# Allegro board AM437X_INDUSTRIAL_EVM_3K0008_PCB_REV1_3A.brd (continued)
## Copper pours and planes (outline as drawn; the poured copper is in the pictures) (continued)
(no net) on BOTTOM: 123.7,66.8 123.7,66.17 121.41,63.88 118.75,63.88 118.49,64.14 118.49,65.15 118.75,65.41 120.02,65.41 120.33,65.72 120.33,67.24 120.91,67.82 122.68,67.82
(no net) on BOTTOM: 120.4,79.63 114.43,79.63 113.66,78.87 112.27,78.87 112.01,79.12 112.01,79.5 114.68,82.17 115.19,82.17 116.33,83.31 116.33,84.45 118.24,86.36 118.24,86.74 118.62,87.12 120.14,87.12 120.65,86.61 120.65,79.88
(no net) on BOTTOM: 52.2,54.61 51.56,53.98 49.66,53.98 49.15,54.48 49.15,56.77 50.93,58.55 51.94,58.55 52.2,58.29
(no net) on BOTTOM: 52.32,76.83 51.43,75.95 49.78,75.95 49.28,76.45 49.28,78.99 51.05,80.77 52.07,80.77 52.32,80.52
(no net) on BOTTOM: 116.08,61.78 116.08,57.91 117.23,56.77 117.23,55.63 117.1,55.5 113.29,55.5 113.16,55.63 113.16,58.17 112.15,59.18 111.51,59.18 110.88,59.81 110.88,66.68 112.78,68.58 114.81,68.58 115.19,68.2 117.23,68.2 117.61,68.58 119.64,68.58 119.89,68.33 119.89,65.86 119.7,65.66 115.63,65.66 115.25,65.28 115.25,62.61
(no net) on BOTTOM: 120.52,77.85 114.3,77.85 113.79,77.34 113.79,72.64 114.17,72.26 118.62,72.26 121.03,74.68 121.03,77.34
(no net) on BOTTOM: 113.16,85.34 115.44,85.34 115.7,85.6 115.7,89.28 115.44,89.53 113.28,89.53 112.9,89.15 112.9,85.6
(no net) on BOTTOM: 54.99,72.52 54.99,69.98 54.36,69.34 52.96,69.34 52.45,69.85 52.45,73.91 52.7,74.17 53.34,74.17
(no net) on BOTTOM: 43.05,47.75 44.58,47.75 44.83,47.5 44.83,46.48 44.58,46.23 43.56,46.23 42.8,46.99 42.8,47.5
(no net) on BOTTOM: 113.28,83.44 113.03,83.69 113.03,84.71 113.28,84.96 114.43,84.96 115.06,84.33 115.06,83.69 114.81,83.44
(no net) on BOTTOM: 129.85,66.64 129.85,67.82 130.11,68.07 133.03,68.07 133.28,67.82 133.28,66.55 133.03,66.29 130.2,66.29
(no net) on BOTTOM: 121.41,82.55 124.08,82.55 124.46,82.93 124.46,86.11 124.08,86.49 121.41,86.49 121.03,86.11 121.03,82.93
(no net) on BOTTOM: 37.34,53.34 43.56,53.34 44.07,53.85 44.07,58.55 43.56,59.05 39.37,59.05 36.83,56.52 36.83,53.85
(no net) on BOTTOM: 44.7,45.85 42.42,45.85 42.16,45.59 42.16,41.91 42.42,41.66 44.58,41.66 44.96,42.04 44.96,45.59
(no net) on BOTTOM: 118.24,40.51 112.01,40.51 111.51,40 111.51,35.31 111.76,35.05 116.46,35.05 118.75,37.34 118.75,40
(no net) on BOTTOM: 109.6,51.18 98.68,51.18 97.92,50.42 97.92,48.64 98.42,48.13 103.12,48.13 103.63,47.62 103.63,45.47 104.52,44.58 109.6,44.58 110.24,45.21 110.24,50.55
(no net) on BOTTOM: 59.31,109.98 60.58,111.25 63.25,111.25 63.5,111.51 66.8,111.51 67.06,111.25 67.06,110.24 66.8,109.98 64.64,109.98 61.85,107.19 61.85,105.79 62.1,105.54 62.74,105.54 62.99,105.28 62.99,104.77 60.96,102.74 54.86,102.74 53.34,104.27 53.26,104.27 53.26,106.55 56.69,109.98
(no net) on BOTTOM: 116.59,61.85 119.13,61.85 119.64,61.34 121.66,61.34 121.92,61.09 121.92,60.71 121.67,60.45 116.84,60.45 116.59,60.71
(no net) on BOTTOM: 124.33,59.94 130.82,59.94 131.57,59.19 131.57,54.1 129.8,52.32 124.59,52.32 123.57,53.34 123.57,59.18
(no net) on BOTTOM: 110.87,48.01 113.16,48.01 113.41,48.26 113.41,51.94 113.16,52.2 111,52.2 110.62,51.82 110.62,48.26
(no net) on BOTTOM: 36.7,48.39 33.66,48.39 33.4,48.13 33.4,45.09 33.78,44.7 36.45,44.7 36.83,45.09 36.83,48.26
(no net) on BOTTOM: 22.48,67.06 26.03,67.06 26.29,66.8 26.29,65.79 26.03,65.53 25.15,65.53 23.62,64.01 22.48,64.01 22.1,64.39 22.1,66.67
(no net) on BOTTOM: 119.13,45.21 121.79,45.21 122.17,45.59 122.17,48.77 121.79,49.15 119.13,49.15 118.75,48.77 118.75,45.59
(no net) on BOTTOM: 52.2,64.14 51.31,63.25 49.66,63.25 49.15,63.75 49.15,66.29 50.8,67.95 51.94,67.95 52.2,67.69
(no net) on BOTTOM: 138.66,66.04 138.66,70.1 138.27,70.48 135.06,70.48 134.81,70.23 134.81,65.41 135.19,65.02 136.84,65.02 136.97,65.15 136.97,66.04
(no net) on BOTTOM: 114.17,104.01 110.62,104.01 110.49,103.89 110.49,102.49 110.74,102.23 117.35,102.23 117.6,102.49 117.6,104.27 117.47,104.39 114.55,104.39
(no net) on BOTTOM: 22.48,92.33 25.91,92.33 26.03,92.2 26.03,91.06 25.78,90.8 25.15,90.8 23.62,89.28 22.48,89.28 22.1,89.66 22.1,91.95
(no net) on BOTTOM: 20.57,56.64 20.57,52.83 19.94,52.2 9.4,52.2 8.89,52.7 8.89,55.24 9.4,55.75 13.46,55.75 14.99,57.28 19.94,57.28
AM437X_VDDS on L4_SIG2: 75.56,72.77 76.33,72.01 86.36,72.01 87.25,71.12 87.25,66.22 73.91,66.22 73.28,65.59 73.28,64.77 74.3,63.75 76.71,63.75 77.85,62.61 77.85,61.34 76.38,59.87 69.55,59.87 67.69,61.72 67.69,69.09 70.48,71.88 74.17,71.88 75.06,72.77
FTDI_VPHY on BOTTOM (solid shape): 121.8,59.18 121.8,58.42 121.67,58.3 120.78,58.3 120.65,58.42 120.27,58.42 119.77,58.42 119.51,58.42 119.26,58.17 116.72,58.17 116.72,59.57 116.84,59.69 121.29,59.69
FTDI_VPLL on BOTTOM (solid shape): 119.64,61.34 120.27,61.34 121.66,61.34 121.92,61.09 121.92,60.86 121.52,60.45 116.84,60.45 116.59,60.71 116.59,61.85 119.13,61.85
MOT_OUT1 on TOP (solid shape): 40.89,28.07 40.91,28.05 40.91,27.25 41.07,27.08 41.07,26.89 41.08,26.82 41.1,26.76 41.12,26.7 41.15,26.64 41.19,26.59 41.24,26.54 41.29,26.49 41.32,26.48 41.32,25.82 36.45,20.95 36.45,19.05 34.16,16.76 30.48,16.76 29.84,17.4 29.84,19.56 34.92,24.64 36.45,24.64 36.45,24.58 36.46,24.53 36.48,24.48 36.51,24.43 36.55,24.38 36.59,24.34 36.63,24.31 36.68,24.29 36.73,24.27 36.79,24.26 36.84,24.26 36.9,24.26 36.95,24.28 37,24.3 37.05,24.33 37.1,24.36 37.13,24.4 37.16,24.45 37.19,24.5 37.2,24.55 37.21,24.61 37.21,24.67 37.2,24.72 37.19,24.77 37.16,24.82 37.13,24.87 37.1,24.91 37.05,24.95 37,24.98 36.95,25 36.9,25.01 36.84,25.02 36.79,25.02 36.73,25.01 36.68,24.99 36.63,24.96 36.59,24.93 36.55,24.89 36.51,24.85 36.48,24.8 36.46,24.75 36.45,24.69 36.45,24.64 34.92,24.64 35.58,25.29 35.62,25.3 35.68,25.32 35.74,25.35 35.79,25.38 35.81,25.4 37.21,25.4 37.41,25.21 38.41,25.21 38.6,25.4 38.61,25.4 40.64,27.43 40.64,29.72 40.89,29.72
MOT_OUT2 on TOP (solid shape): outline of 153 points within 37.85,16.76 42.93,27.3
MOT_OUT3 on TOP (solid shape): 44.32,26.8 45.34,26.8 46.61,25.53 46.61,22.35 47.24,21.72 50.93,21.72 51.56,21.08 51.56,18.54 51.37,18.17 51.56,17.79 51.56,17.4 50.8,16.64 47.6,16.64 47.43,16.81 47.43,16.81 43.69,20.55 43.69,26.42 43.31,26.8 43.31,27.18 43.56,27.43 43.69,27.43
MOT_PGNDTOTAL on BOTTOM: 39.5,24.64 47.37,24.64 51.94,29.21 52.96,29.21 53.21,28.96 53.21,25.15 48.39,20.32 41.27,20.32 39.12,22.48 39.12,24.26
MOT_PGNDTOTAL on L3_SIG1: 50.55,33.78 58.8,33.78 59.82,32.77 59.82,28.96 57.4,26.54 52.32,26.54 51.18,25.4 51.18,23.88 52.2,22.86 58.67,22.86 59.56,21.97 59.56,20.83 58.8,20.07 49.02,20.07 46.48,22.61 46.48,29.72
MOTOR_OUT1 on TOP: 33.91,15.24 34.29,14.86 34.29,12.19 34.04,11.94 30.23,11.94 26.92,8.64 26.92,3.43 25.65,2.16 23.62,2.16 21.97,3.81 21.97,9.78 27.43,15.24
MOTOR_OUT2 on TOP: 37.21,14.22 41.78,14.22 42.29,13.72 42.29,12.45 38.99,9.14 34.29,9.14 32,6.86 32,3.43 30.73,2.16 28.7,2.16 27.43,3.43 27.43,8.51 30.48,11.56 34.54,11.56
MOTOR_OUT3 on TOP: 44.7,14.22 49.4,14.22 49.91,13.72 49.91,12.45 49.02,11.56 46.61,11.56 37.21,2.16 33.78,2.16 32.51,3.43 32.51,6.6 34.42,8.51 38.99,8.51
MTRA_GND on L3_SIG1: 2.79,34.04 2.79,45.34 6.6,49.15 12.95,49.15 20.07,42.04 20.07,29.46 19.05,28.45 8.38,28.45
USBJTAG_ENN on BOTTOM: 127.64,73.15 128.4,73.15 128.4,71.63 127.64,71.63
VADD33_PRUETH0 on BOTTOM (solid shape): 26.03,92.2 26.03,91.06 25.78,90.8 25.15,90.8 25.07,90.73 24.33,91.48 23.43,91.48 23.43,90.58 24,90 24,89.66 23.62,89.28 23.6,89.29 23.45,89.3 23.31,89.28 23.3,89.28 23.14,89.28 23.14,89.33 22.43,89.33 22.1,89.66 22.1,91.29 22.1,91.31 22.1,91.95 22.48,92.33 25.91,92.33
VADD33_PRUETH1 on BOTTOM (solid shape): 25.98,67.02 26.08,66.84 26.26,66.72 26.29,66.71 26.29,66.45 26.26,66.44 25.97,66.12 26.07,65.7 26.1,65.63 26.07,65.57 26.03,65.53 25.15,65.53 25.07,65.46 24.33,66.21 23.43,66.21 23.43,65.31 24,64.73 24,64.39 23.62,64.01 23.01,64.01 23.01,64.06 22.43,64.06 22.1,64.39 22.1,66.02 22.1,66.04 22.1,66.68 22.48,67.06 25.97,67.06
VAM437X_DDR_VREF on BOTTOM: 81.91,63.5 82.63,63.5 83.06,63.07 83.06,62.74 82.55,62.23 82.55,59.44 82.04,58.93 82.04,56.77 81.79,56.52 81.28,56.52 80.64,57.15 80.64,58.29 81.03,58.67 81.03,60.07 81.66,60.71 81.66,63.25
VENDAT on BOTTOM: 17.65,42.04 17.65,36.83 14.86,34.04 6.73,34.04 4.95,35.81 4.95,47.12 5.21,47.37 6.35,47.37 6.6,47.12 12.57,47.12
VETH1_AVDDH on TOP: 35.94,71.37 35.94,72.9 36.45,73.41 38.99,73.41 39.88,74.3 40.89,74.3 41.27,73.91 41.27,71.5 40.89,71.12 36.2,71.12
VETH1_AVDDH on BOTTOM: 36.2,71.12 44.83,71.12 45.47,71.75 45.47,80.26 44.58,81.15 38.86,81.15 38.73,81.03 38.73,78.99 39.24,78.49 40.51,78.49 41.15,77.85 41.15,73.79 40.77,73.41 36.45,73.41 35.94,72.9 35.94,71.37
VETH1_AVDDH on L4_SIG2: 34.92,80.26 38.61,80.26 39.24,80.9 40.64,80.9 41.27,80.26 43.81,80.26 44.96,79.12 44.96,74.3 41.78,71.12 36.7,71.12 26.8,81.03 26.8,94.23 31.75,99.19 38.48,99.19 41.02,96.65 44.96,96.65 46.86,98.55 47.5,98.55 48.13,97.92 48.13,96.95 44.91,93.73 34.16,93.73 33.02,92.58 33.02,89.28 30.86,87.12 30.86,84.33
VETH1_AVDDL on L4_SIG2: 52.96,100.84 52.96,99.44 51.82,98.3 50.8,98.3 50.04,99.06 46.1,99.06 44.32,97.28 41.27,97.28 40.51,98.04 40.51,99.95 42.63,102.07 47.1,102.07 47.5,102.46 51.33,102.46
VETH1_AVDDL_PLL on L5_PWR: 52.2,97.92 52.83,97.28 52.83,94.87 52.32,94.36 46.23,94.36 44.7,92.84 36.96,92.84 32.38,97.41 32.38,99.19 33.02,99.82 36.07,99.82 38.86,97.03 44.96,97.03 46.58,98.65 49.68,98.65 50.42,97.92
VETH1_AVDDL_PMOS on TOP: 30.99,74.68 30.73,74.93 30.73,76.45 30.99,76.71 35.18,76.71 35.43,76.45 35.43,74.93 35.18,74.68
VETH1_AVDDL_PMOS on BOTTOM: 30.99,73.15 35.69,73.15 36.83,74.3 39.12,74.3 39.24,74.42 39.24,75.44 39.12,75.56 36.83,75.56 35.69,76.71 30.99,76.71 30.73,76.45 30.73,73.41
VETH1_AVDDL_PMOS on L5_PWR: 34.92,72.9 38.61,72.9 40.69,74.98 40.69,82.7 45.17,87.19 52.9,87.19 56.01,90.3 56.01,98.81 55.5,99.31 54.1,99.31 53.34,98.55 53.34,94.49 52.64,93.79 46.77,93.79 45.11,92.13 35.89,92.13 34.67,90.91 34.67,78.11 33.15,76.58 33.15,74.68
VETH1_DVDDH on TOP: 35.05,82.8 35.05,84.07 34.29,84.84 33.02,84.84 32.64,84.45 32.64,80.9 32.89,80.64 34.29,80.64 34.54,80.9 34.54,82.3
VETH1_DVDDH on L4_SIG2: 38.23,81.15 39.24,82.17 40.26,82.17 41.27,81.15 46.99,81.15 48.77,82.93 48.77,86.13 46.79,88.11 46.79,90.42 47.07,90.7 51.46,90.7 52.2,91.44 52.2,95.5 51.56,96.14 50.67,96.14 50.27,95.73 47.9,95.73 44.88,92.71 38.1,92.71 31.5,86.11 31.5,85.34 35.69,81.15
VETH1_DVDDL on TOP: 45.97,96.9 47.12,96.9 49.28,94.74 52.83,94.74 53.21,94.36 53.21,90.04 50.55,87.38 43.69,87.38 42.67,88.39 42.67,93.6
VMTR_PWRIN on TOP: 3.3,16.38 10.79,16.38 12.45,18.03 12.45,23.11 11.05,24.51 3.17,24.51 1.91,23.24 1.91,17.78
VPWRIN_JCK on TOP: 123.95,25.65 134.49,25.65 138.05,22.1 138.05,13.59 136.53,12.07 134.24,12.07 133.22,13.08 131.83,13.08 130.81,12.07 127,12.07 126.36,12.7 126.36,15.49 122.94,18.92 122.94,24.64
VPWRIN_PREFUSE on TOP: 124.84,16.13 124.84,11.94 124.08,11.18 115.82,11.18 114.55,12.45 114.55,16.13 115.19,16.76 124.21,16.76
VUSB_FTDI on BOTTOM (solid shape): 133.04,68.04 133.13,67.85 133.28,67.71 133.28,67.08 133.28,67.06 133.28,66.55 133.03,66.29 131.54,66.29 131.54,66.29 130.94,66.29 130.2,66.29 129.85,66.64 129.85,67.82 130.11,68.07 133.03,68.07
VUSB_JTAG on BOTTOM: 136.62,64.01 136.62,64.55 136.5,64.68 134.97,64.68 134.72,64.93 134.72,65.44 134.46,65.69 133.45,65.69 133.23,65.91 131.7,65.91 131.44,65.66 131.44,64.77 132.21,64.01
N11220684 on TOP: 94.83,15.3 95.93,15.3 96.14,15.1 96.14,14.48 96.39,14.22 96.77,14.22 97.03,14.48 97.03,16 97.31,16.28 97.31,16.54 97.13,16.71 95.41,16.71 94.8,16.1 94.8,15.33
N12220066 on L3_SIG1: 21.72,91.69 28.83,91.69 31.75,88.77 31.75,87.25 31.37,86.87 30.48,86.87 29.72,87.63 20.7,87.63 20.32,88.01 20.32,90.3
N12225158 on L4_SIG2: 21.72,66.29 30.1,66.29 31.62,64.77 31.62,61.85 31.12,61.34 25.65,61.34 24.38,62.61 20.83,62.61 20.45,62.99 20.45,65.02
N14814919 on TOP: 87.12,90.8 88.9,90.8 89.41,90.3 89.41,88.27 89.03,87.88 87,87.88 86.61,88.27 86.61,90.3
N14814919 on BOTTOM: 87,90.8 89.03,90.8 89.53,90.3 89.53,88.14 89.28,87.88 86.74,87.88 86.49,88.14 86.49,90.3
N15838226 on BOTTOM: 127.25,98.93 128.52,98.93 128.91,99.31 128.91,103.63 128.52,104.01 127.25,104.01 126.87,103.63 126.87,99.31
N16087451 on TOP (solid shape): 56.59,113.84 56.59,111.2 55.37,109.98 53.37,109.98 53.09,110.27 53.09,112.52 54.61,114.05 56.39,114.05
N16087466 on TOP (solid shape): 60.32,114.81 60.32,110.24 60.07,109.98 58.04,109.98 56.97,111.05 56.97,114 56.9,114.08 56.9,114.68 57.39,115.18 58.43,115.18 58.44,115.19 59.68,115.19 59.94,115.19
N16087466 on BOTTOM (solid shape): 60.32,114.81 60.32,111.51 59.94,111.12 55.12,111.12 54.61,111.63 54.61,114.05 55.75,115.19 59.94,115.19
N16279225 on BOTTOM: 69.47,81.15 71.5,81.15 71.63,81.03 71.63,79.76 71.37,79.5 69.27,79.5 68.88,79.12 67.64,79.12 67.06,79.71 67.06,80.77 67.18,80.9 69.22,80.9
N16279225 on L3_SIG1: 74.8,69.22 71.37,69.22 67.18,73.41 67.18,80.26 67.95,81.03 69.06,81.03 69.88,80.21 69.88,74.63 72.36,72.14 75.18,72.14 75.69,71.63 75.69,70.1
N16286128 on TOP (solid shape): 117.14,76.15 117.14,73.2 117.22,73.12 117.22,72.64 116.84,72.26 114.17,72.26 113.79,72.64 113.79,76.96 114.05,77.22 116.08,77.22
N16286128 on BOTTOM (solid shape): 121.03,77.34 121.03,74.68 119.34,72.98 119.3,72.99 118.88,72.91 118.8,72.49 118.82,72.46 118.62,72.26 118.16,72.26 117.86,72.42 117.55,72.26 114.17,72.26 113.79,72.64 113.79,77.34 114.3,77.85 120.52,77.85
N16286350 on TOP (solid shape): 121.03,77.09 121.03,74.68 119.51,73.15 117.73,73.15 117.53,73.36 117.53,76.12 118.62,77.22 120.9,77.22
N16287061 on TOP (solid shape): 44.07,58.55 44.07,54.23 43.81,53.98 41.78,53.98 40.72,55.04 40.72,57.99 40.64,58.07 40.64,58.55 41.15,59.05 43.56,59.05
N16287061 on BOTTOM (solid shape): 44.07,58.55 44.07,53.85 43.56,53.34 37.34,53.34 36.83,53.85 36.83,56.52 37.08,56.77 37.13,56.77 37.19,56.78 37.24,56.8 37.29,56.83 37.33,56.86 37.37,56.9 37.41,56.95 37.43,57 37.45,57.05 37.46,57.1 37.47,57.15 38.84,58.52 39.65,58.52 39.65,58.47 39.66,58.41 39.68,58.36 39.71,58.31 39.75,58.27 39.79,58.23 39.83,58.2 39.88,58.17 39.93,58.15 39.99,58.14 40.04,58.14 40.1,58.15 40.15,58.16 40.21,58.18 40.25,58.21 40.3,58.25 40.33,58.29 40.36,58.33 40.39,58.39 40.4,58.44 40.41,58.49 40.41,58.55 40.4,58.6 40.39,58.66 40.36,58.71 40.33,58.76 40.3,58.8 40.25,58.83 40.21,58.86 40.15,58.88 40.1,58.9 40.04,58.9 39.99,58.9 39.93,58.89 39.88,58.87 39.83,58.85 39.79,58.82 39.75,58.78 39.71,58.73 39.68,58.68 39.66,58.63 39.65,58.58 39.65,58.52 38.84,58.52 39.37,59.05 43.56,59.05
N16287283 on TOP (solid shape): 40.34,57.84 40.34,55.07 39.24,53.98 36.96,53.98 36.83,54.1 36.83,56.52 37.08,56.77 37.1,56.77 37.35,56.88 37.46,57.13 37.47,57.15 38.35,58.04 40.13,58.04
N16288012 on TOP (solid shape): 114.86,38.81 114.86,35.86 114.94,35.78 114.94,35.31 114.43,34.8 112.01,34.8 111.51,35.31 111.51,39.62 111.76,39.88 113.79,39.88
N16288012 on BOTTOM (solid shape): 118.75,40 118.75,37.34 116.46,35.05 111.76,35.05 111.51,35.31 111.51,40 112.01,40.51 118.24,40.51
N16288234 on TOP (solid shape): 118.75,39.75 118.75,37.34 117.22,35.81 115.44,35.81 115.24,36.02 115.24,38.79 116.33,39.88 118.62,39.88
N16738683 on BOTTOM (solid shape): 44.83,47.5 44.83,46.48 44.58,46.23 43.56,46.23 42.8,46.99 42.8,47.5 43.05,47.75 44.58,47.75
N16739248 on BOTTOM (solid shape): 112.78,46.86 112.78,46.35 112.52,46.1 111,46.1 110.74,46.35 110.74,47.37 111,47.62 112.01,47.62
N16740119 on BOTTOM (solid shape): 115.06,84.33 115.06,83.69 114.81,83.44 113.28,83.44 113.03,83.69 113.03,84.71 113.28,84.96 114.43,84.96
N17015946 on BOTTOM: 3.43,15.24 9.91,15.24 10.29,14.86 10.29,13.46 9.91,13.08 6.6,13.08 5.33,11.81 3.3,11.81 2.67,12.45 2.67,14.48
N17049952 on TOP (solid shape): 24.77,53.98 29.21,53.98 29.59,53.59 29.59,52.07 29.21,51.69 23.24,51.69 22.99,51.94 22.99,53.98 23.24,54.23 24.51,54.23
N17049952 on BOTTOM (solid shape): 30.35,57.28 30.61,57.02 30.61,55.75 29.59,54.74 29.59,52.07 29.21,51.69 24.64,51.69 24.26,52.07 24.26,54.36 27.18,57.28 29.84,57.28
N17050085 on TOP (solid shape): 24.51,58.55 24.51,56.77 24.26,56.52 23.11,56.52 22.99,56.64 22.99,58.67 23.11,58.8 24.26,58.8
N17050085 on BOTTOM: 24,56.64 26.03,56.64 26.92,57.53 30.35,57.53 30.61,57.78 30.61,58.42 30.35,58.67 24.13,58.67 23.75,58.29 23.75,56.9
N17134629 on BOTTOM: 66.93,107.31 67.31,106.93 67.31,105.54 67.18,105.41 66.04,105.41 65.91,105.54 65.91,107.19 66.04,107.31
N17135096 on BOTTOM: 68.96,108.84 68.71,108.58 66.04,108.58 65.91,108.71 65.91,109.47 66.17,109.73 66.93,109.73 67.31,110.11 67.31,111.38 66.8,111.89 65.79,111.89 65.53,112.14 65.53,114.81 65.79,115.06 66.8,115.06 68.96,112.9

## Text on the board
BOTTOM: PN#: 3K0008 | LAYER 6  SECONDARY SIDE | 6
Ref Des/Silkscreen Bottom: 1 | 2 | 5 | 3 | 7 | 6 | 9 | 8 | 10 | 59 | 60 | 39 | 40 | SD/MMC0
TOP: LAYER 1 - PRIMARY SIDE | 1 | 6
Ref Des/Silkscreen Top: A | 1 | 2 | 7 | 6 | 10 | 9 | 8 | ARM MPU | AM437X Industrial EVM | REV 1.3A | ASSM PN#:4P0040 | 40 | 39 | 3 | SN#:__________ | 125VAC, 125VDC | 4A Slow Blow | GND | V24_0MTR | Industrial | I/O Connector | VDD_MPU | Expansion Connector | V24_0D | Warm Reset | User Switch | 24.0VDC | 1.5A | PRUETH1 | PRUETH0 | Gb Ethernet | Fault | Motor | Camera
PAGE_OUTLINE: TI | AM437X_INDUSTRIAL_EVM_3K0008_REV1_3A
DIMENSION: SILKSCREEN TOP | 1 | 2
DISPLAY_BOTTOM: 2 | ASSEMBLY BOTTOM
DEVICE_TYPE_BOTTOM: ASSEMBLY TOP | 1 | 2
User.8: FABRICATION DRAWING | 1
User.9: LAYER 2 - GROUND PLANE | 2 | 6
User.10: LAYER 3 - SIGNAL LAYER 1 | 3 | 6
User.11: LAYER 4 - SIGNAL LAYER 2 | 4 | 6
User.12: LAYER 5 - POWER LAYER | 5 | 6
User.13: SOLDER MASK BOTTOM | 2
User.14: SOLDER MASK TOP | 1 | 2
User.15: SOLDER PASTE BOTTOM | 2
User.16: SOLDER PASTE TOP | 1 | 2
User.17: SILKSCREEN BOTTOM | 2
User.19: LAYER 6-SIGNAL LAYER 2 | 6 | 8
User.20: LAYER 7 -GROUND PLANE | 7 | 8
User.24: BOARD NAME: | BOARD NO: 3K0008 | CUSTOMER NAME: | AM437X_INDUSTRIAL_EVM | TEXAS INSTRUMENTS | REV: 1.3A | DESCRIPTION: | DATE: 07/18/2014 | SH | OF
User.25: OF | SH | DATE:07/18/2014 | DESCRIPTION: | TEXAS INSTRUMENTS | REV:1.3A | AM437X_INDUSTRIAL_EVM | BOARD NAME: | CUSTOMER NAME: | BOARD NO:3K0008
User.26: L1_TOP | L3_SIG1 | L6_SIG2 | L8_BOTTOM | LAYERS | in mils | TRACE | WIDTH | 5.124 | SINGLE-ENDED | +/-10% | TARGET | Ohms | 50 | 4.01 | EDGE-COUPLED DIFFERENTIAL | SPACE | 4.525 | 5.110 | 90 | 4.0 | 9.22 | 7.6 | 100
User.30: CLASS 2 AND WORKMANSHIP SHALL CONFORM TO | IPC-A-600, CLASS 2. CURRENT REVISIONS. | 2. THE PWB SHALL BE FABRICATED TO IPC-6012, | 9. ALL VIAS TO HAVE SOLDERMASK. | 4. BOARD MATERIAL & CONSTRUCTION TO BE UL94V0 CERTIFIED | AND MARKED ON TOP SIDE OF FINISHED BOARD. | 3. BOARD MATERIAL SHALL BE 180 Tg/350 Td ISOLA FR-370 HR | OR EQUIVALENT, RoHS COMPLIANT AND LEAD FREE | ASSEMBLY CAPABLE.  BOARD MATERIAL SHALL | MEET OR EXCEED IPC-4101B. COLOR: NATURAL. | 5. MINIMUM COPPER WALL THICKNESS OF PLATED-THRU | HOLES TO BE .001 INCH, WITH A MINIMUM | ANNULAR RING OF .002 INCH. | FAB NOTES: | 6. OVERALL BOARD THICKNESS TO BE .0625 +/- 10% | AND APPLIES AFTER ALL LAMINATION AND PLATING | 1. ALL DIMENSIONS ARE IN INCHES, UNLESS | OTHERWISE NOTED. | SUPPLIED IPC-D-356 NETLIST. | PROCESSES, MEASURED FROM COPPER TO COPPER. | 8. BOARD MUST BE ELECTRICALLY TESTED USING | 7. MAX. WARP & TWIST TO BE .0075 INCHES PER INCH. | 2. APPLY LPI SOLDERMASK OVER BARE COPPER (SMOBC), | COLOR: BLACK SOLDERMASK SHALL | CONFORM TO IPC-SM-840, CLASS H. CURRENT REV. | 3. SOLDERMASK ARTWORK HAS ZERO (0) OVERSIZED PADS. | FABRICATION VENDOR IS ALLOWED TO ADJUST THE COMPONENT | SOLDERMASK PADS TO MEET THEIR TOOLING REQUIREMENTS. | 4. APPLY LPI SILKSCREEN OR EQUIVALENT PER THE ARTWORK. | IMMERSION GOLD, NICKEL 150 MICROINCHES THK MIN | GOLD 5-15 MICROINCHES THK MIN. | COLOR: WHITE. | PROCESS NOTES: | 1. PLATE ALL EXPOSED AREAS WITH ELECTROLESS | IMPEDANCE REQUIREMENT :- THIS DESIGN MAY NOT CONTAIN ALL THE FEATURES | NOTE : | LISTED IN THE ABOVE TABLE
User.31: FIGURE | SIZE | 10.0 | 12.0 | 20.0 | 33.0 | 35.0 | 35.04 | 40.0 | 40.16 | 45.67 | 47.0 | 50.0 | 51.18 | 67.0 | 120.0 | 140.0 | 33.46 | 66.93 | 125.98 | 138.0 | DRILL CHART: TOP to BOTTOM | ALL UNITS ARE IN MILS | TOLERANCE | +2.0/-2.0 | +3.0/-3.0 | +7.87/-7.87 | +0.0/-0.0 | +3.15/-3.15 | +3.94/-3.94 | PLATED | NON-PLATED | QTY | 1282 | 1023 | 123 | 60 | 40 | 26 | 23 | 12 | 10 | 8 | 4 | 3 | 6 | 2 | 1
